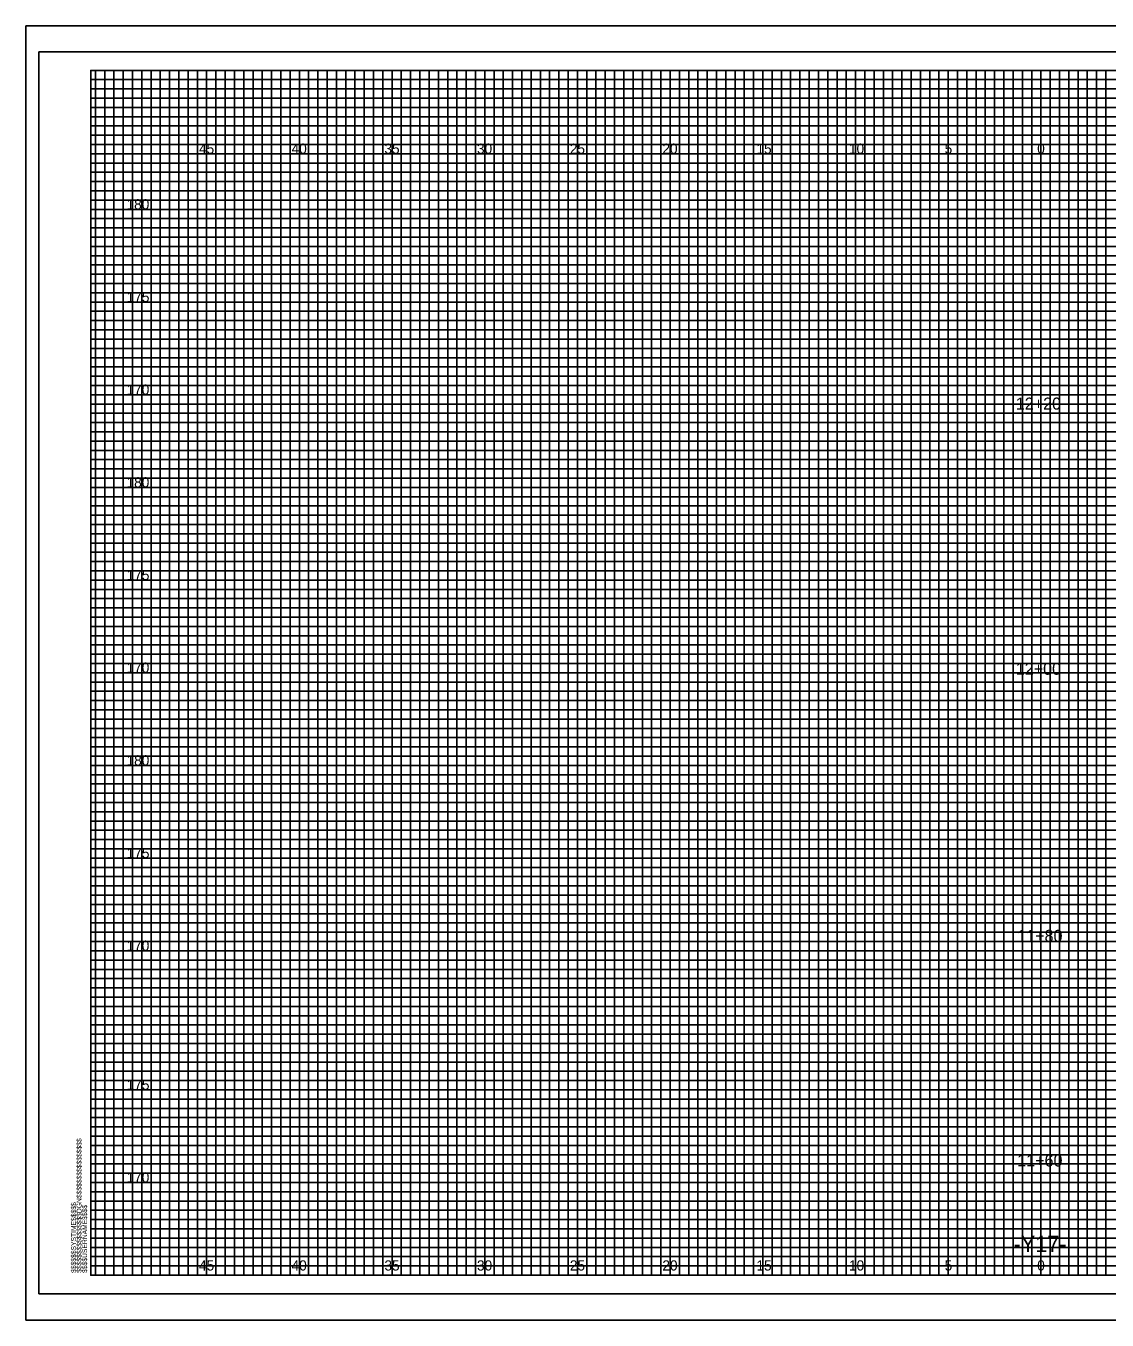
# Model space of a CAD drawing. Extents: x -4 to 103, y -2 to 209.
# Drawn here: x -3.5 to 54.8, y 68.4 to 138.2 of the extents above; entities that cross this region are included whole.
import ezdxf

# ---------------------------------------------------------------- set-up
doc = ezdxf.new("R2010")
doc.units = 0
for name, color, linetype in [('Prop XS Alignment Label', 7, 'Continuous'), ('Prop XS Elevation Labels', 7, 'Continuous'), ('Prop XS Offset Labels', 7, 'Continuous'), ('Prop XS Station Labels', 7, 'Continuous'), ('Sheet Cross Section CELL', 7, 'Continuous'), ('Sheet Cross Section Grid Major CELL', 7, 'Continuous'), ('Sheet Cross Section Grid Middle CELL', 7, 'Continuous'), ('Sheet Cutting Line CELL', 7, 'Continuous'), ('Sheet DOT Grid CELL', 7, 'Continuous'), ('Sheet Plot Border Inside CELL', 7, 'Continuous'), ('Sheet Plot Border Outside CELL', 7, 'Continuous')]:
    doc.layers.add(name, color=color, linetype=linetype)

msp = doc.modelspace()

# ---------------------------------------------------------------- linework, layer by layer
at = {"layer": 'Sheet Cross Section CELL'}
msp.add_lwpolyline([(102.5, 135.825), (0, 135.825), (0, 70.825), (102.5, 70.825)], close=True, dxfattribs=at)
at = {"layer": 'Sheet Cross Section Grid Major CELL'}
for points in [[(1.25, 70.825), (1.25, 135.825), (3.75, 135.825), (3.75, 70.825), (6.25, 70.825), (6.25, 135.825), (8.75, 135.825), (8.75, 70.825), (11.25, 70.825), (11.25, 135.825), (13.75, 135.825), (13.75, 70.825), (16.25, 70.825), (16.25, 135.825), (18.75, 135.825), (18.75, 70.825), (21.25, 70.825), (21.25, 135.825), (23.75, 135.825), (23.75, 70.825), (26.25, 70.825), (26.25, 135.825), (28.75, 135.825), (28.75, 70.825), (31.25, 70.825), (31.25, 135.825), (33.75, 135.825), (33.75, 70.825), (36.25, 70.825), (36.25, 135.825), (38.75, 135.825), (38.75, 70.825), (41.25, 70.825), (41.25, 135.825), (43.75, 135.825), (43.75, 70.825), (46.25, 70.825), (46.25, 135.825), (48.75, 135.825), (48.75, 70.825), (51.25, 70.825), (51.25, 135.825), (53.75, 135.825), (53.75, 70.825)], [(102.5, 130.825), (0, 130.825), (0, 133.325), (74.25, 133.325)], [(102.5, 125.825), (0, 125.825), (0, 128.325), (102.5, 128.325)], [(102.5, 120.825), (0, 120.825), (0, 123.325), (102.5, 123.325)], [(102.5, 115.825), (0, 115.825), (0, 118.325), (102.5, 118.325)], [(102.5, 110.825), (0, 110.825), (0, 113.325), (102.5, 113.325)], [(102.5, 105.825), (0, 105.825), (0, 108.325), (102.5, 108.325)], [(102.5, 100.825), (0, 100.825), (0, 103.325), (102.5, 103.325)], [(102.5, 95.825), (0, 95.825), (0, 98.325), (102.5, 98.325)], [(102.5, 90.825), (0, 90.825), (0, 93.325), (102.5, 93.325)], [(102.5, 85.825), (0, 85.825), (0, 88.325), (102.5, 88.325)], [(102.5, 80.825), (0, 80.825), (0, 83.325), (102.5, 83.325)], [(102.5, 75.825), (0, 75.825), (0, 78.325), (102.5, 78.325)], [(0, 73.325), (102.5, 73.325)]]:
    msp.add_lwpolyline(points, dxfattribs=at)
at = {"layer": 'Sheet Cross Section Grid Middle CELL'}
for points in [[(0.25, 70.825), (0.25, 135.825), (0.75, 135.825), (0.75, 70.825), (1.75, 70.825), (1.75, 135.825), (2.25, 135.825), (2.25, 70.825), (2.75, 70.825), (2.75, 135.825), (3.25, 135.825), (3.25, 70.825), (4.25, 70.825), (4.25, 135.825), (4.75, 135.825), (4.75, 70.825), (5.25, 70.825), (5.25, 135.825), (5.75, 135.825), (5.75, 70.825), (6.75, 70.825), (6.75, 135.825), (7.25, 135.825), (7.25, 70.825), (7.75, 70.825), (7.75, 135.825), (8.25, 135.825), (8.25, 70.825), (9.25, 70.825), (9.25, 135.825), (9.75, 135.825), (9.75, 70.825), (10.25, 70.825), (10.25, 135.825), (10.75, 135.825), (10.75, 70.825), (11.75, 70.825), (11.75, 135.825), (12.25, 135.825), (12.25, 70.825), (12.75, 70.825), (12.75, 135.825), (13.25, 135.825), (13.25, 70.825), (14.25, 70.825), (14.25, 135.825), (14.75, 135.825), (14.75, 70.825), (15.75, 70.825), (15.25, 70.825), (15.25, 135.825), (15.75, 135.825), (15.75, 70.825), (16.75, 70.825), (16.75, 135.825), (17.25, 135.825), (17.25, 70.825), (17.75, 70.825), (17.75, 135.825), (18.25, 135.825), (18.25, 70.825), (19.25, 70.825), (19.25, 135.825), (19.75, 135.825), (19.75, 70.825), (20.25, 70.825), (20.25, 135.825), (20.75, 135.825), (20.75, 70.825), (21.75, 70.825), (21.75, 135.825), (22.25, 135.825), (22.25, 70.825), (22.75, 70.825), (22.75, 135.825), (23.25, 135.825), (23.25, 70.825), (24.25, 70.825), (24.25, 135.825), (24.75, 135.825), (24.75, 70.825), (25.25, 70.825), (25.25, 135.825), (25.75, 135.825), (25.75, 70.825), (26.75, 70.825), (26.75, 135.825), (27.25, 135.825), (27.25, 70.825), (27.75, 70.825), (27.75, 135.825), (28.25, 135.825), (28.25, 70.825), (29.25, 70.825), (29.25, 135.825), (29.75, 135.825), (29.75, 70.825), (30.25, 70.825), (30.25, 135.825), (30.75, 135.825), (30.75, 70.825)], [(30.75, 70.825), (31.75, 70.825), (31.75, 135.825), (32.25, 135.825), (32.25, 70.825), (32.75, 70.825), (32.75, 135.825), (33.25, 135.825), (33.25, 70.825), (34.25, 70.825), (34.25, 135.825), (34.75, 135.825), (34.75, 70.825), (35.25, 70.825), (35.25, 135.825), (35.75, 135.825), (35.75, 70.825), (36.75, 70.825), (36.75, 135.825), (37.25, 135.825), (37.25, 70.825), (37.75, 70.825), (37.75, 135.825), (37.75, 70.825)], [(38.25, 135.825), (38.25, 70.825), (39.25, 70.825), (39.25, 135.825), (39.75, 135.825), (39.75, 70.825), (40.25, 70.825), (40.25, 135.825), (40.75, 135.825), (40.75, 70.825), (41.75, 70.825), (41.75, 135.825), (42.25, 135.825), (42.25, 70.825), (42.75, 70.825), (42.75, 135.825), (43.25, 135.825), (43.25, 70.825), (43.75, 70.825), (44.25, 70.825), (44.25, 135.825), (44.75, 135.825), (44.75, 70.825), (45.25, 70.825), (45.25, 135.825), (45.75, 135.825), (45.75, 70.825), (46.75, 70.825), (46.75, 135.825), (47.25, 135.825), (47.25, 70.825), (47.75, 70.825), (47.75, 135.825), (48.25, 135.825), (48.25, 70.825), (49.25, 70.825), (49.25, 135.825), (49.75, 135.825), (49.75, 70.825), (50.25, 70.825), (50.25, 135.825), (50.75, 135.825), (50.75, 70.825), (51.75, 70.825), (51.75, 135.825), (52.25, 135.825), (52.25, 70.825), (52.75, 70.825), (52.75, 135.825), (53.25, 135.825), (53.25, 70.825), (54.25, 70.825), (54.25, 135.825), (54.75, 135.825), (54.75, 70.825), (55.25, 70.825)], [(0, 132.825), (0, 133.825), (74.25, 133.825), (74.25, 134.325), (0, 134.325), (0, 134.825), (74.25, 134.825), (74.25, 135.325), (0, 135.325)], [(102.5, 132.825), (0, 132.825)], [(102.5, 131.825), (0, 131.825), (0, 132.325), (102.5, 132.325)], [(102.5, 130.325), (0, 130.325), (0, 131.325), (102.5, 131.325)], [(102.5, 129.325), (0, 129.325), (0, 129.825), (102.5, 129.825)], [(102.5, 127.825), (0, 127.825), (0, 128.825), (102.5, 128.825)], [(102.5, 126.825), (0, 126.825), (0, 127.325), (102.5, 127.325)], [(102.5, 125.325), (0, 125.325), (0, 126.325), (102.5, 126.325)], [(102.5, 124.325), (0, 124.325), (0, 124.825), (102.5, 124.825)], [(0, 123.825), (102.5, 123.825)], [(102.5, 122.825), (0, 122.825)], [(102.5, 121.825), (0, 121.825), (0, 122.325), (102.5, 122.325)], [(102.5, 120.325), (0, 120.325), (0, 121.325), (102.5, 121.325)], [(102.5, 119.325), (0, 119.325), (0, 119.825), (102.5, 119.825)], [(102.5, 117.825), (0, 117.825), (0, 118.825), (102.5, 118.825)], [(102.5, 116.825), (0, 116.825), (0, 117.325), (102.5, 117.325)], [(102.5, 115.325), (0, 115.325), (0, 116.325), (102.5, 116.325)], [(102.5, 114.325), (0, 114.325), (0, 114.825), (102.5, 114.825)], [(102.5, 112.825), (0, 112.825), (0, 113.825), (102.5, 113.825)], [(102.5, 111.825), (0, 111.825), (0, 112.325), (102.5, 112.325)], [(102.5, 110.325), (0, 110.325), (0, 111.325), (102.5, 111.325)], [(102.5, 109.325), (0, 109.325), (0, 109.825), (102.5, 109.825)], [(102.5, 107.825), (0, 107.825), (0, 108.825), (102.5, 108.825)], [(102.5, 106.825), (0, 106.825), (0, 107.325), (102.5, 107.325)], [(102.5, 105.325), (0, 105.325), (0, 106.325), (102.5, 106.325)], [(102.5, 104.325), (0, 104.325), (0, 104.825), (102.5, 104.825)], [(102.5, 102.825), (0, 102.825), (0, 103.825), (102.5, 103.825)], [(102.5, 101.825), (0, 101.825), (0, 102.325)], [(0, 102.325), (102.5, 102.325)], [(102.5, 100.325), (0, 100.325), (0, 101.325), (102.5, 101.325)], [(102.5, 99.325), (0, 99.325), (0, 99.825), (102.5, 99.825)], [(102.5, 97.825), (0, 97.825), (0, 98.825), (102.5, 98.825)], [(102.5, 96.825), (0, 96.825), (0, 97.325), (102.5, 97.325)], [(102.5, 95.325), (0, 95.325), (0, 96.325), (102.5, 96.325)], [(102.5, 94.325), (0, 94.325), (0, 94.825), (102.5, 94.825)], [(102.5, 92.825), (0, 92.825), (0, 93.825), (102.5, 93.825)], [(102.5, 91.825), (0, 91.825), (0, 92.325), (102.5, 92.325)], [(102.5, 90.325), (0, 90.325), (0, 91.325), (102.5, 91.325)], [(102.5, 89.325), (0, 89.325), (0, 89.825), (102.5, 89.825)], [(102.5, 87.825), (0, 87.825), (0, 88.825), (102.5, 88.825)], [(102.5, 86.825), (0, 86.825), (0, 87.325), (102.5, 87.325)], [(102.5, 85.325), (0, 85.325), (0, 86.325), (102.5, 86.325)], [(102.5, 84.325), (0, 84.325), (0, 84.825), (102.5, 84.825)], [(102.5, 82.825), (0, 82.825), (0, 83.825), (102.5, 83.825)], [(102.5, 81.825), (0, 81.825), (0, 82.325), (102.5, 82.325)], [(102.5, 80.325), (0, 80.325), (0, 81.325), (102.5, 81.325)], [(102.5, 79.325), (0, 79.325), (0, 79.825), (102.5, 79.825)], [(102.5, 77.825), (0, 77.825), (0, 78.825), (102.5, 78.825)], [(102.5, 76.825), (0, 76.825), (0, 77.325), (102.5, 77.325)], [(102.5, 75.325), (0, 75.325), (0, 76.325), (102.5, 76.325)], [(102.5, 74.325), (0, 74.325), (0, 74.825), (102.5, 74.825)], [(102.5, 72.825), (0, 72.825), (0, 73.825), (102.5, 73.825)], [(102.5, 71.825), (0, 71.825), (0, 72.325), (102.5, 72.325)], [(0, 71.325), (102.5, 71.325)]]:
    msp.add_lwpolyline(points, dxfattribs=at)
at = {"layer": 'Sheet Cutting Line CELL'}
for p, q in [((-3.5, 138.225), (103.4, 138.225)), ((-3.5, 138.225), (-3.5, 68.4)), ((-3.5, 68.4), (103.4, 68.4))]:
    msp.add_line(p, q, dxfattribs=at)
at = {"layer": 'Sheet DOT Grid CELL'}
for p, q in [((1.25, 70.825), (1.25, 135.825)), ((3.75, 70.825), (3.75, 135.825)), ((6.25, 70.825), (6.25, 135.825)), ((8.75, 70.825), (8.75, 135.825)), ((11.25, 70.825), (11.25, 135.825)), ((13.75, 70.825), (13.75, 135.825)), ((16.25, 70.825), (16.25, 135.825)), ((18.75, 70.825), (18.75, 135.825)), ((21.25, 70.825), (21.25, 135.825)), ((23.75, 70.825), (23.75, 135.825)), ((26.25, 70.825), (26.25, 135.825)), ((28.75, 70.825), (28.75, 135.825)), ((31.25, 70.825), (31.25, 135.825)), ((33.75, 70.825), (33.75, 135.825)), ((36.25, 70.825), (36.25, 135.825)), ((38.75, 70.825), (38.75, 135.825)), ((41.25, 70.825), (41.25, 135.825)), ((43.75, 70.825), (43.75, 135.825)), ((46.25, 70.825), (46.25, 135.825)), ((48.75, 70.825), (48.75, 135.825)), ((51.25, 70.825), (51.25, 135.825)), ((53.75, 70.825), (53.75, 135.825)), ((0, 133.325), (74.25, 133.325)), ((0, 130.825), (102.5, 130.825)), ((0, 128.325), (102.5, 128.325)), ((0, 125.825), (102.5, 125.825)), ((0, 123.325), (102.5, 123.325)), ((0, 120.825), (102.5, 120.825)), ((0, 118.325), (102.5, 118.325)), ((0, 115.825), (102.5, 115.825)), ((0, 113.325), (102.5, 113.325)), ((0, 110.825), (102.5, 110.825)), ((0, 108.325), (102.5, 108.325)), ((0, 105.825), (102.5, 105.825)), ((0, 103.325), (102.5, 103.325)), ((0, 100.825), (102.5, 100.825)), ((0, 98.325), (102.5, 98.325)), ((0, 95.825), (102.5, 95.825)), ((0, 93.325), (102.5, 93.325)), ((0, 90.825), (102.5, 90.825)), ((0, 88.325), (102.5, 88.325)), ((0, 85.825), (102.5, 85.825)), ((0, 83.325), (102.5, 83.325)), ((0, 80.825), (102.5, 80.825)), ((0, 78.325), (102.5, 78.325)), ((0, 75.825), (102.5, 75.825)), ((0, 73.325), (102.5, 73.325))]:
    msp.add_line(p, q, dxfattribs=at)
at = {"layer": 'Sheet Plot Border Inside CELL'}
msp.add_lwpolyline([(103, 136.825), (-2.8, 136.825), (-2.8, 69.825), (103, 69.825)], close=True, dxfattribs=at)
at = {"layer": 'Sheet Plot Border Outside CELL'}
msp.add_lwpolyline([(103.4, 138.225), (-3.5, 138.225), (-3.5, 68.4), (103.4, 68.4)], close=True, dxfattribs=at)

# ---------------------------------------------------------------- texts
at = {"layer": 'Prop XS Alignment Label'}
msp.add_text('-Y17-', height=0.875, dxfattribs=at).set_placement((49.77311, 72.075))
at = {"layer": 'Prop XS Elevation Labels'}
for s, p in [('180', (1.92958, 128.325)), ('175', (1.93825, 123.325)), ('170', (1.92958, 118.325)), ('180', (1.92958, 113.325)), ('175', (1.93825, 108.325)), ('170', (1.92958, 103.325)), ('180', (1.92958, 98.325)), ('175', (1.93825, 93.325)), ('170', (1.92958, 88.325)), ('175', (1.93825, 80.825)), ('170', (1.92958, 75.825))]:
    msp.add_text(s, height=0.55, dxfattribs=at).set_placement(p)
at = {"layer": 'Prop XS Offset Labels'}
for s, p in [('45', (5.83992, 131.325)), ('40', (10.83125, 131.325)), ('35', (15.83992, 131.325)), ('30', (20.83125, 131.325)), ('25', (25.83992, 131.325)), ('20', (30.83125, 131.325)), ('15', (35.90575, 131.325)), ('10', (40.89708, 131.325)), ('5', (46.05742, 131.325)), ('0', (51.04875, 131.325)), ('0', (51.04875, 131.325)), ('45', (5.83992, 71.075)), ('40', (10.83125, 71.075)), ('35', (15.83992, 71.075)), ('30', (20.83125, 71.075)), ('25', (25.83992, 71.075)), ('20', (30.83125, 71.075)), ('15', (35.90575, 71.075)), ('10', (40.89708, 71.075)), ('5', (46.05742, 71.075)), ('0', (51.04875, 71.075)), ('0', (51.04875, 71.075))]:
    msp.add_text(s, height=0.55, dxfattribs=at).set_placement(p)
at = {"layer": 'Prop XS Station Labels'}
for s, p in [('12+20', (49.89337, 117.5219)), ('12+00', (49.89337, 103.2173)), ('11+80', (49.97117, 88.8059)), ('11+60', (49.97117, 76.6917))]:
    msp.add_text(s, height=0.65, dxfattribs=at).set_placement(p)
at = {"layer": 'Sheet Cross Section CELL'}
for s, p in [('$$$$$$$$$$$$$$$$DGN$$$$$$$$$$$$$$$$', (-0.5, 70.95)), ('$$$$$$SYSTIME$$$$$', (-0.7973, 70.9497)), ('$$$$USERNAME$$$$', (-0.2, 70.95))]:
    msp.add_text(s, height=0.2625, rotation=90, dxfattribs=at).set_placement(p)
at = {"layer": 'Sheet Cross Section Grid Major CELL'}
msp.add_text('040397', height=0.0025, rotation=90, dxfattribs=at).set_placement((-0.0007, 135.8114))

doc.saveas('drawing.dxf')
